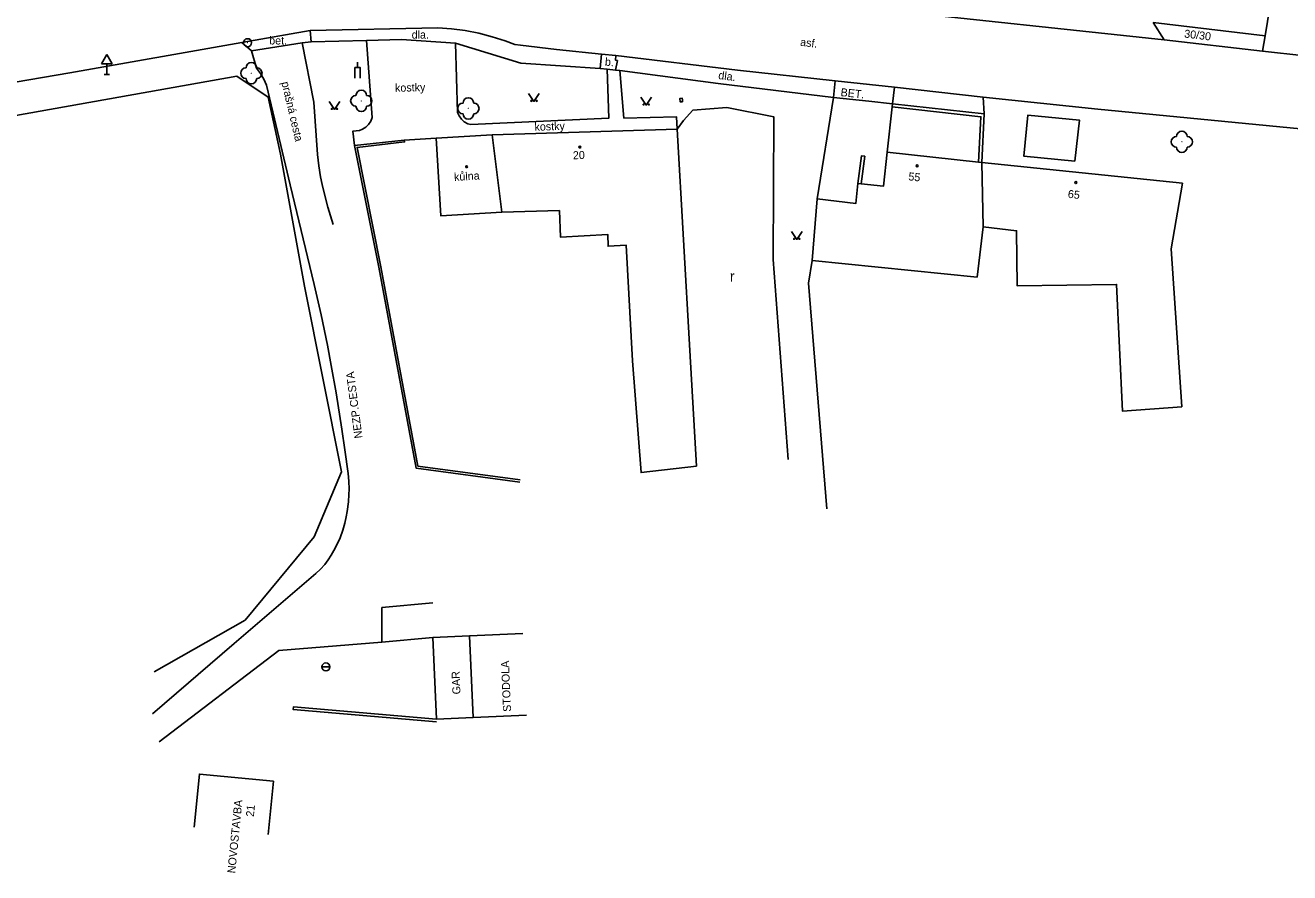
# Model space of a CAD drawing. Extents: x -544674 to -541478, y -1199076 to -1195527.
# Drawn here: x -544299.5 to -544181, y -1198400.2 to -1198320.8 of the extents above; entities that cross this region are included whole.
import ezdxf

# ---------------------------------------------------------------- set-up
doc = ezdxf.new("R2010")
doc.units = 0
for name, color, linetype in [('BUDOVY_MĚŘ', 7, 'Continuous'), ('BUDOVY_NEMĚŘ', 7, 'Continuous'), ('MAP_ZN_BP', 7, 'Continuous'), ('OBVOD_PILÍŘE', 7, 'Continuous'), ('POMOC_POPIS', 7, 'Continuous'), ('ROZHRANÍ_PLOCH', 7, 'Continuous'), ('ZELEŇ', 7, 'Continuous'), ('ZN_BUDOV', 7, 'Continuous'), ('ZN_DOPLŇKOVÉ', 7, 'Continuous'), ('ZN_KULTUR', 7, 'Continuous'), ('Č_POPIS_ORIENT', 7, 'Continuous')]:
    doc.layers.add(name, color=color, linetype=linetype)

msp = doc.modelspace()

# ---------------------------------------------------------------- linework, layer by layer
at = {"layer": 'BUDOVY_MĚŘ'}
for points in [[(-544255.75, -1198331.08), (-544260.99, -1198331.39)], [(-544255.75, -1198331.08), (-544238.4, -1198330.52)], [(-544238.4, -1198330.52), (-544237.22, -1198351.26), (-544236.58, -1198362.12)], [(-544218.73, -1198332.69), (-544219.08, -1198335.89), (-544221.17, -1198335.66)], [(-544210.17, -1198333.63), (-544218.73, -1198332.69)], [(-544209.87, -1198333.66), (-544210.17, -1198333.63)], [(-544191.07, -1198335.58), (-544209.87, -1198333.66)], [(-544221.47, -1198335.63), (-544221.68, -1198337.5), (-544225.28, -1198337.05)], [(-544221.17, -1198335.66), (-544221.47, -1198335.63)], [(-544225.28, -1198337.05), (-544225.77, -1198342.83)], [(-544261.29, -1198378.17), (-544257.85, -1198378.02)], [(-544260.94, -1198385.82), (-544261.29, -1198378.17)], [(-544252.86, -1198377.8), (-544257.85, -1198378.02)], [(-544257.52, -1198385.66), (-544257.85, -1198378.02)], [(-544257.52, -1198385.66), (-544260.94, -1198385.82)], [(-544252.52, -1198385.45), (-544257.52, -1198385.66)], [(-544276.72, -1198396.62), (-544276.23, -1198391.64), (-544283.17, -1198390.96), (-544283.66, -1198395.94)]]:
    msp.add_lwpolyline(points, dxfattribs=at)
at = {"layer": 'BUDOVY_NEMĚŘ'}
for points in [[(-544260.99, -1198331.39), (-544260.56, -1198338.64), (-544254.82, -1198338.3)], [(-544254.82, -1198338.3), (-544255.75, -1198331.08)], [(-544209.75, -1198339.7), (-544209.87, -1198333.66)], [(-544209.75, -1198339.7), (-544206.61, -1198340.05), (-544206.55, -1198345.21), (-544197.23, -1198345.08), (-544196.67, -1198356.96), (-544191.13, -1198356.54), (-544192.13, -1198341.75), (-544191.07, -1198335.58)], [(-544236.58, -1198362.12), (-544241.79, -1198362.72), (-544242.59, -1198352.25), (-544243.17, -1198341.41), (-544244.87, -1198341.5), (-544244.9, -1198340.42), (-544249.34, -1198340.64), (-544249.43, -1198338.16), (-544254.82, -1198338.3)], [(-544225.77, -1198342.83), (-544210.31, -1198344.4), (-544209.75, -1198339.7)]]:
    msp.add_lwpolyline(points, dxfattribs=at)
at = {"layer": 'MAP_ZN_BP'}
for radius in [0.375, 0.0005]:
    msp.add_circle((-544278.66, -1198322.43), radius, dxfattribs=at)
at = {"layer": 'OBVOD_PILÍŘE'}
msp.add_lwpolyline([(-544237.92, -1198327.8), (-544237.91, -1198327.96), (-544238.13, -1198327.97), (-544238.15, -1198327.65), (-544237.93, -1198327.64), (-544237.92, -1198327.8)], dxfattribs=at)
at = {"layer": 'ROZHRANÍ_PLOCH'}
for points in [[(-544183.33, -1198321.8), (-544182.44, -1198316.37)], [(-544230.61, -1198317.92), (-544219.73, -1198319.28), (-544192.77, -1198322.17)], [(-544192.77, -1198322.17), (-544193.81, -1198320.55)], [(-544193.81, -1198320.55), (-544183.33, -1198321.8)], [(-544279.2, -1198322.41), (-544272.79, -1198321.3)], [(-544272.79, -1198321.3), (-544260.83, -1198321.05)], [(-544272.79, -1198321.3), (-544272.69, -1198322.34)], [(-544260.83, -1198321.05), (-544259.54, -1198321.14)], [(-544259.54, -1198321.14), (-544258.26, -1198321.3)], [(-544258.26, -1198321.3), (-544257, -1198321.54)], [(-544257, -1198321.54), (-544255.75, -1198321.87)], [(-544255.75, -1198321.87), (-544254.52, -1198322.26)], [(-544183.56, -1198323.22), (-544183.33, -1198321.8)], [(-544295.31, -1198325.25), (-544279.2, -1198322.41)], [(-544279.2, -1198322.41), (-544278.28, -1198323.2)], [(-544278.28, -1198323.2), (-544273.54, -1198322.44)], [(-544277.81, -1198324.81), (-544278.28, -1198323.2)], [(-544273.54, -1198322.44), (-544272.69, -1198322.34)], [(-544273.54, -1198322.44), (-544272.45, -1198328)], [(-544272.69, -1198322.34), (-544267.51, -1198322.23)], [(-544267.51, -1198322.23), (-544264.23, -1198322.12), (-544259.16, -1198322.47)], [(-544267.51, -1198322.23), (-544266.98, -1198329.44)], [(-544259.16, -1198322.47), (-544253.04, -1198324.34), (-544245.62, -1198324.85)], [(-544258.98, -1198328.97), (-544259.16, -1198322.47)], [(-544254.52, -1198322.26), (-544253.62, -1198322.61)], [(-544253.62, -1198322.61), (-544253.08, -1198322.67)], [(-544253.08, -1198322.67), (-544249.71, -1198323.08)], [(-544249.71, -1198323.08), (-544245.48, -1198323.5)], [(-544192.77, -1198322.17), (-544183.56, -1198323.22)], [(-544183.56, -1198323.22), (-544179.59, -1198323.67)], [(-544245.62, -1198324.85), (-544245.48, -1198323.5)], [(-544245.48, -1198323.5), (-544244.14, -1198323.62)], [(-544244.14, -1198323.62), (-544244.19, -1198324.06), (-544244.01, -1198324.1), (-544244.17, -1198325)], [(-544244.14, -1198323.62), (-544232.76, -1198325.02), (-544223.59, -1198325.99)], [(-544295.31, -1198325.25), (-544335.93, -1198332.2)], [(-544277.43, -1198325.31), (-544277.81, -1198324.81)], [(-544277.12, -1198325.85), (-544277.43, -1198325.31)], [(-544244.96, -1198324.92), (-544244.82, -1198329.51), (-544257.74, -1198330.11)], [(-544245.62, -1198324.85), (-544244.96, -1198324.92)], [(-544244.96, -1198324.92), (-544244.17, -1198325)], [(-544244.17, -1198325), (-544243.79, -1198325.04)], [(-544243.79, -1198325.04), (-544234.57, -1198326.24), (-544223.77, -1198327.56)], [(-544243.79, -1198325.04), (-544243.4, -1198329.49), (-544238.47, -1198329.37), (-544238.4, -1198330.52)], [(-544276.88, -1198326.42), (-544277.12, -1198325.85)], [(-544274.65, -1198335.75), (-544276.88, -1198326.42)], [(-544223.77, -1198327.56), (-544223.59, -1198325.99)], [(-544218.05, -1198326.61), (-544223.59, -1198325.99)], [(-544218.05, -1198326.61), (-544218.23, -1198328.16)], [(-544209.72, -1198327.53), (-544218.05, -1198326.61)], [(-544089.24, -1198339.43), (-544143.65, -1198334.03), (-544198.99, -1198328.67), (-544209.72, -1198327.53)], [(-544209.63, -1198329.1), (-544209.72, -1198327.53)], [(-544272.45, -1198328), (-544272.09, -1198332.91)], [(-544258.98, -1198328.97), (-544258.84, -1198329.3), (-544258.62, -1198329.6), (-544258.35, -1198329.84), (-544258.03, -1198330.02), (-544257.74, -1198330.11)], [(-544218.26, -1198328.45), (-544218.73, -1198332.69)], [(-544218.23, -1198328.16), (-544218.26, -1198328.45)], [(-544266.98, -1198329.44), (-544267.11, -1198329.78), (-544267.31, -1198330.09), (-544267.57, -1198330.35), (-544267.88, -1198330.54), (-544268.16, -1198330.65)], [(-544201.16, -1198333.52), (-544200.7, -1198329.7), (-544205.56, -1198329.23), (-544205.93, -1198333.06), (-544201.16, -1198333.52)], [(-544268.16, -1198330.65), (-544268.79, -1198330.72), (-544268.64, -1198332.06)], [(-544272.09, -1198332.91), (-544271.98, -1198333.97)], [(-544271.98, -1198333.97), (-544271.81, -1198335.01)], [(-544271.81, -1198335.01), (-544271.67, -1198335.71)], [(-544287.56, -1198385.31), (-544279.92, -1198378.74), (-544272.27, -1198372.17), (-544271.82, -1198371.75), (-544271.43, -1198371.32), (-544271.1, -1198370.88), (-544270.81, -1198370.45), (-544270.56, -1198370.03), (-544270.35, -1198369.62), (-544269.99, -1198368.82), (-544269.73, -1198368.1), (-544269.55, -1198367.44), (-544269.41, -1198366.86), (-544269.32, -1198366.35), (-544269.2, -1198365.45), (-544269.16, -1198364.77), (-544269.15, -1198364.27), (-544269.17, -1198363.53), (-544269.24, -1198362.81), (-544269.53, -1198360.59), (-544269.81, -1198358.65), (-544270.35, -1198355.24), (-544270.81, -1198352.69), (-544271.18, -1198350.78), (-544271.77, -1198347.92), (-544272.42, -1198345.08), (-544274.65, -1198335.75)], [(-544271.67, -1198335.71), (-544271.45, -1198336.63)], [(-544271.45, -1198336.63), (-544271.12, -1198337.85)], [(-544271.12, -1198337.85), (-544270.64, -1198339.47)], [(-544266.07, -1198375.36), (-544261.3, -1198374.93)], [(-544266.07, -1198375.36), (-544266.06, -1198378.6)], [(-544286.93, -1198387.95), (-544275.74, -1198379.37), (-544266.06, -1198378.6)], [(-544266.06, -1198378.6), (-544261.29, -1198378.17)]]:
    msp.add_lwpolyline(points, dxfattribs=at)
at = {"layer": 'ZELEŇ'}
msp.add_lwpolyline([(-544238.4, -1198330.52), (-544237.82, -1198329.71), (-544236.95, -1198328.76), (-544233.76, -1198328.51), (-544229.34, -1198329.38), (-544229.4, -1198342.74), (-544228.02, -1198361.5)], dxfattribs=at)
for centre in [(-544278.3, -1198325.29), (-544268, -1198327.88), (-544257.97, -1198328.59), (-544191.12, -1198331.72)]:
    msp.add_circle(centre, 0.0005, dxfattribs=at)
for centre, start, end in [((-544278.3, -1198324.79), 0, 179.99999), ((-544278.8, -1198325.29), 89.99999, 269.99999), ((-544277.8, -1198325.29), 270, 89.99999), ((-544278.3, -1198325.79), 179.99999, 359.99999), ((-544268.5, -1198327.88), 89.99999, 269.99999), ((-544268, -1198327.38), 0, 179.99999), ((-544267.5, -1198327.88), 270, 89.99999), ((-544257.97, -1198328.09), 0, 179.99999), ((-544268, -1198328.38), 179.99999, 359.99999), ((-544258.47, -1198328.59), 89.99999, 269.99999), ((-544257.97, -1198329.09), 179.99999, 359.99999), ((-544257.47, -1198328.59), 270, 89.99999), ((-544191.62, -1198331.72), 89.99999, 269.99999), ((-544191.12, -1198331.22), 0, 179.99999), ((-544190.62, -1198331.72), 270, 89.99999), ((-544191.12, -1198332.22), 179.99999, 359.99999)]:
    msp.add_arc(centre, 0.5, start, end, dxfattribs=at)
at = {"layer": 'ZN_BUDOV'}
for centre in [(-544247.52, -1198332.21), (-544215.92, -1198333.97), (-544258.13, -1198334.05), (-544201.05, -1198335.54)]:
    msp.add_circle(centre, 0.0875, dxfattribs=at)
at = {"layer": 'ZN_DOPLŇKOVÉ'}
for p, q in [((-544291.84, -1198323.544), (-544292.34, -1198324.41)), ((-544292.34, -1198324.41), (-544291.34, -1198324.41)), ((-544291.84, -1198323.544), (-544291.34, -1198324.41)), ((-544291.84, -1198325.41), (-544291.84, -1198324.41)), ((-544268.34, -1198324.77), (-544268.34, -1198324.27)), ((-544292.09, -1198325.41), (-544291.59, -1198325.41)), ((-544271.695, -1198380.92), (-544270.945, -1198380.92))]:
    msp.add_line(p, q, dxfattribs=at)
for points in [[(-544275.58, -1198332.88), (-544276.73, -1198327.54), (-544279.67, -1198325.58), (-544309.17, -1198330.81), (-544315.36, -1198332.04), (-544329.99, -1198333.93)], [(-544268.59, -1198325.77), (-544268.59, -1198324.77), (-544268.09, -1198324.77), (-544268.09, -1198325.77)], [(-544223.77, -1198327.56), (-544225.28, -1198337.05)], [(-544218.23, -1198328.16), (-544220.46, -1198327.91), (-544223.77, -1198327.56)], [(-544210.17, -1198333.63), (-544209.94, -1198329.37), (-544218.26, -1198328.45)], [(-544209.63, -1198329.1), (-544218.23, -1198328.16)], [(-544209.87, -1198333.66), (-544209.63, -1198329.1)], [(-544263.99, -1198331.55), (-544260.99, -1198331.39)], [(-544263.99, -1198331.55), (-544268.64, -1198332.06), (-544266.36, -1198343.47)], [(-544263.99, -1198331.55), (-544263.95, -1198331.73), (-544268.4, -1198332.25), (-544266.16, -1198343.43)], [(-544287.4, -1198381.38), (-544278.87, -1198376.53), (-544272.43, -1198368.73), (-544269.85, -1198362.63), (-544273.32, -1198345.24), (-544275.58, -1198332.88)], [(-544221.17, -1198335.66), (-544220.83, -1198333.07), (-544221.13, -1198333.03), (-544221.47, -1198335.63)], [(-544225.77, -1198342.83), (-544226.09, -1198344.97), (-544224.38, -1198366.11)], [(-544266.36, -1198343.47), (-544262.86, -1198362.29), (-544253.16, -1198363.6)], [(-544266.16, -1198343.43), (-544262.69, -1198362.11), (-544253.13, -1198363.4)], [(-544260.94, -1198385.82), (-544274.36, -1198384.67), (-544274.38, -1198384.92), (-544260.96, -1198386.07)]]:
    msp.add_lwpolyline(points, dxfattribs=at)
msp.add_circle((-544271.32, -1198380.92), 0.375, dxfattribs=at)
at = {"layer": 'ZN_KULTUR'}
for points in [[(-544271.01, -1198327.94), (-544270.51, -1198328.69), (-544270.01, -1198327.94)], [(-544252.32, -1198327.19), (-544251.82, -1198327.94), (-544251.32, -1198327.19)], [(-544241.8, -1198327.53), (-544241.3, -1198328.28), (-544240.8, -1198327.53)], [(-544227.7, -1198340.12), (-544227.2, -1198340.87), (-544226.7, -1198340.12)]]:
    msp.add_lwpolyline(points, dxfattribs=at)
for centre in [(-544252.07, -1198327.89), (-544251.57, -1198327.89), (-544270.76, -1198328.64), (-544270.26, -1198328.64), (-544241.55, -1198328.23), (-544241.05, -1198328.23), (-544227.45, -1198340.82), (-544226.95, -1198340.82)]:
    msp.add_circle(centre, 0.05, dxfattribs=at)

# ---------------------------------------------------------------- texts
at = {"layer": 'POMOC_POPIS'}
for s, p in [('bet.', (-544276.63, -1198322.6)), ('dla.', (-544263.28, -1198322.05))]:
    msp.add_text(s, height=0.75, dxfattribs=at).set_placement(p)
for s, rotation, p in [('30/30', 353.35001, (-544190.93, -1198321.94)), ('asf.', 353.46998, (-544226.91, -1198322.72)), ('b.', 354.87997, (-544245.2, -1198324.57)), ('dla.', 352.80999, (-544234.58, -1198325.83)), ('prašná cesta', 283.22003, (-544275.48, -1198326.16)), ('kostky', 1.59002, (-544264.83, -1198327.04)), ('BET.', 353.95998, (-544223.12, -1198327.43)), ('kostky', 1.85002, (-544251.76, -1198330.69)), ('kůlna', 3.39002, (-544259.29, -1198335.39)), ('NEZP.CESTA', 97.42001, (-544267.88, -1198359.46)), ('STODOLA', 92.50003, (-544253.96, -1198385.12)), ('GAR', 92.62, (-544258.7, -1198383.48)), ('NOVOSTAVBA', 84.40001, (-544279.81, -1198400.29))]:
    msp.add_text(s, height=0.75, rotation=rotation, dxfattribs=at).set_placement(p)
at = {"layer": 'ZN_KULTUR'}
msp.add_text('r', height=1, dxfattribs=at).set_placement((-544233.468, -1198344.822))
at = {"layer": 'Č_POPIS_ORIENT'}
for s, rotation, p in [('20', 2.15999, (-544248.16, -1198333.36)), ('55', 353.72999, (-544216.77, -1198335.32)), ('65', 353.72999, (-544201.83, -1198336.96)), ('21', 84.40001, (-544278.07, -1198394.99))]:
    msp.add_text(s, height=0.75, rotation=rotation, dxfattribs=at).set_placement(p)

doc.saveas('drawing.dxf')
